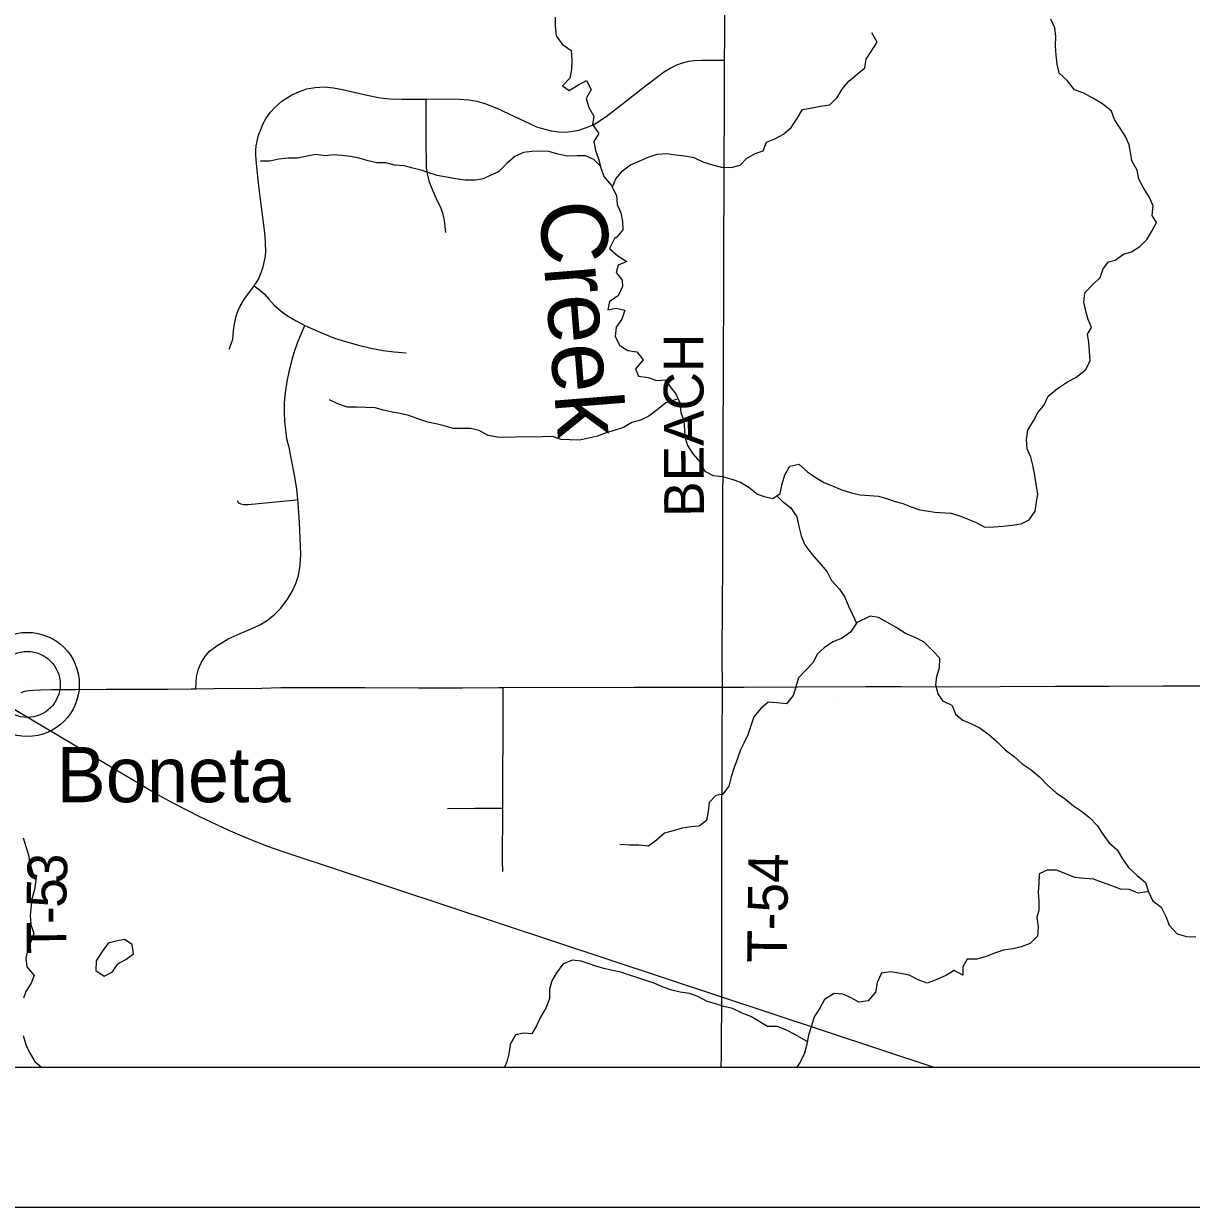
# Model space of a CAD drawing. Extents: x 0 to 34, y 0 to 22.
# Drawn here: x 6.998 to 7.832, y 14 to 14.845 of the extents above; entities that cross this region are included whole.
import ezdxf

# ---------------------------------------------------------------- set-up
doc = ezdxf.new("R2010")
doc.units = 0
for name, color, linetype in [('GM_X_Minor_Lake', 7, 'Continuous'), ('GM_X_Minor_River', 7, 'Continuous'), ('GM_X_Minor_River_Text', 7, 'Continuous'), ('GM_X_Rail_Line', 7, 'Continuous'), ('GM_X_Rail_Line_Text', 7, 'Continuous'), ('GM_X_State_Location', 7, 'Continuous'), ('GM_X_State_Route', 7, 'Continuous'), ('GM_X_Township_Road', 7, 'Continuous'), ('GM_X_Township_Road_Text', 7, 'Continuous'), ('GM_X_Unincorporated', 7, 'Continuous'), ('GM_X_Unincorporated_Location', 7, 'Continuous'), ('GM_X_Unincorporated_Text', 7, 'Continuous'), ('SH_Cut_Line', 7, 'Continuous'), ('SH_Data', 7, 'Continuous')]:
    doc.layers.add(name, color=color, linetype=linetype)

msp = doc.modelspace()

# ---------------------------------------------------------------- linework, layer by layer
at = {"layer": 'GM_X_Minor_Lake'}
for points in [[(7.05816, 14.18868), (7.05377, 14.18268), (7.04953, 14.17596), (7.04928, 14.16913), (7.05523, 14.16507), (7.06125, 14.16821), (7.06493, 14.17397), (7.06498, 14.174)], [(7.05812, 14.18863), (7.05377, 14.18268), (7.04953, 14.17596), (7.04928, 14.16913), (7.05523, 14.16507), (7.06125, 14.16821), (7.06493, 14.17397), (7.06706, 14.17503)], [(7.06699, 14.17502), (7.07076, 14.17693), (7.07618, 14.18101), (7.07529, 14.18783), (7.06973, 14.19133), (7.06349, 14.19007), (7.05798, 14.18863)], [(7.06498, 14.174), (7.07076, 14.17693), (7.07618, 14.18101), (7.07529, 14.18783), (7.06973, 14.19133), (7.06349, 14.19007), (7.05816, 14.18868)]]:
    msp.add_lwpolyline(points, dxfattribs=at)
at = {"layer": 'GM_X_Minor_River'}
for points in [[(7.37743, 14.85002), (7.37727, 14.84357), (7.37806, 14.83675), (7.38243, 14.8307), (7.38889, 14.82618), (7.3893, 14.81973), (7.38914, 14.81272), (7.38783, 14.80645), (7.38256, 14.80112), (7.38749, 14.79773), (7.39353, 14.80155), (7.39977, 14.8048), (7.4032, 14.79837), (7.39963, 14.79191), (7.40155, 14.78547), (7.40498, 14.77942), (7.40406, 14.77335), (7.40863, 14.76711), (7.40506, 14.76122), (7.40622, 14.75496), (7.40833, 14.74891), (7.41006, 14.74247), (7.41216, 14.73622), (7.4173, 14.72999), (7.42112, 14.7228), (7.42171, 14.71617), (7.4242, 14.7103), (7.42555, 14.70424), (7.42576, 14.69817), (7.42105, 14.69246), (7.4201, 14.69246), (7.41616, 14.68486), (7.42205, 14.67958), (7.4285, 14.67562), (7.42227, 14.67294), (7.42096, 14.66763), (7.42515, 14.66234), (7.42555, 14.6576), (7.42236, 14.65095), (7.41631, 14.64694), (7.41501, 14.64106), (7.42088, 14.64222), (7.42713, 14.64092), (7.42507, 14.63447), (7.42093, 14.62857), (7.4202, 14.62212), (7.42364, 14.61569), (7.42933, 14.61193), (7.43577, 14.611), (7.44015, 14.60534), (7.43487, 14.59887), (7.43698, 14.59357), (7.4438, 14.59265), (7.44986, 14.59059), (7.45649, 14.591), (7.45954, 14.58608), (7.46353, 14.58117), (7.4664, 14.57473), (7.46718, 14.56772), (7.46929, 14.56167), (7.46989, 14.55503), (7.46991, 14.55029), (7.47201, 14.54405), (7.47564, 14.53818), (7.48096, 14.53214), (7.4842, 14.5259), (7.49028, 14.5227), (7.4969, 14.52197), (7.50354, 14.5201), (7.5098, 14.51785), (7.51606, 14.51409), (7.52195, 14.50937), (7.52669, 14.50769), (7.53294, 14.5062), (7.53823, 14.50982), (7.53952, 14.51666), (7.54139, 14.52311), (7.54496, 14.52938), (7.55139, 14.53074), (7.55766, 14.52527), (7.56374, 14.52112), (7.56962, 14.51773), (7.58214, 14.51248), (7.58896, 14.51023), (7.59521, 14.50893), (7.60203, 14.50839), (7.60847, 14.50785), (7.61473, 14.50598), (7.61946, 14.50449), (7.62572, 14.50281), (7.6316, 14.50037), (7.63785, 14.49831), (7.64259, 14.49738), (7.64865, 14.49646), (7.6598, 14.49574)], [(7.6598, 14.49574), (7.66018, 14.49571), (7.66683, 14.49372), (7.67294, 14.49131), (7.67771, 14.48946), (7.68421, 14.48592), (7.69068, 14.486), (7.69732, 14.48645), (7.70359, 14.48728), (7.71023, 14.48831), (7.71609, 14.49104), (7.72039, 14.49718), (7.72127, 14.50366), (7.72216, 14.50956), (7.72094, 14.51621), (7.72011, 14.52267), (7.7189, 14.52912), (7.71711, 14.53576), (7.71457, 14.54182), (7.71412, 14.54829), (7.71499, 14.55515), (7.7191, 14.56166), (7.72208, 14.56778), (7.72658, 14.57278), (7.72955, 14.57928), (7.73633, 14.58488), (7.74331, 14.58953), (7.74936, 14.59264), (7.75614, 14.59823), (7.75968, 14.60474), (7.75903, 14.61158), (7.75858, 14.61767), (7.75776, 14.62356), (7.76056, 14.62834), (7.75821, 14.63403), (7.75643, 14.64009), (7.75503, 14.64655), (7.75572, 14.65321), (7.76117, 14.65879), (7.76662, 14.66418), (7.76883, 14.6703), (7.77258, 14.67528), (7.77732, 14.67648), (7.78335, 14.68073), (7.78922, 14.68251), (7.79507, 14.68619), (7.80034, 14.69158), (7.80369, 14.69733), (7.80705, 14.70345), (7.80376, 14.70855), (7.80463, 14.71541), (7.80171, 14.72166), (7.79765, 14.72827), (7.79435, 14.73432), (7.79314, 14.74078), (7.78945, 14.74759), (7.78864, 14.75233), (7.78742, 14.75898), (7.78488, 14.76485), (7.78101, 14.77089), (7.77696, 14.77694), (7.7748, 14.783), (7.76828, 14.78825), (7.76158, 14.79217), (7.75508, 14.79591), (7.7484, 14.79811), (7.74339, 14.80452), (7.73743, 14.80998), (7.73603, 14.81643), (7.73539, 14.82289), (7.73474, 14.82973), (7.73505, 14.83639), (7.73422, 14.84247), (7.73149, 14.84872)], [(7.41801, 14.72861), (7.41844, 14.72901), (7.42069, 14.73455), (7.4254, 14.74045), (7.43125, 14.74464), (7.43749, 14.74714), (7.44391, 14.7502), (7.45034, 14.75231), (7.45715, 14.75272), (7.4636, 14.7518), (7.47004, 14.75107), (7.47648, 14.74977), (7.48293, 14.74676), (7.48975, 14.74452), (7.49619, 14.74284), (7.5032, 14.74268), (7.50944, 14.74441), (7.51415, 14.74917), (7.5202, 14.75261), (7.52606, 14.75472), (7.52831, 14.7608), (7.53435, 14.76329), (7.5404, 14.76654), (7.54587, 14.7713), (7.5502, 14.77777), (7.55415, 14.78404), (7.56096, 14.78539), (7.56701, 14.78656), (7.57363, 14.78753), (7.57872, 14.79268), (7.5823, 14.79876), (7.5872, 14.80428), (7.59323, 14.80942), (7.59871, 14.81399), (7.59944, 14.82006), (7.6032, 14.82558), (7.60753, 14.83223), (7.60371, 14.83885)], [(7.4097, 14.74378), (7.40511, 14.74851), (7.39904, 14.75114), (7.39298, 14.75112), (7.38617, 14.7509), (7.37935, 14.7522), (7.3729, 14.75406), (7.3676, 14.75442), (7.36079, 14.7542), (7.35473, 14.75342), (7.34868, 14.75055), (7.34284, 14.74559), (7.33699, 14.73969), (7.33094, 14.73701), (7.32603, 14.73471), (7.32035, 14.73374), (7.31316, 14.73371), (7.30634, 14.73463), (7.29971, 14.73574), (7.29308, 14.73704), (7.28645, 14.73909), (7.28171, 14.74078), (7.27564, 14.74227), (7.26939, 14.74395), (7.26257, 14.74449), (7.25651, 14.74598), (7.25007, 14.74614), (7.24381, 14.74744), (7.23737, 14.74931), (7.23112, 14.75061), (7.22506, 14.75134), (7.21919, 14.7517), (7.21313, 14.7511), (7.20631, 14.75202), (7.20026, 14.75086), (7.19326, 14.7495), (7.18644, 14.74947), (7.18001, 14.74869), (7.17358, 14.74733), (7.16676, 14.7473)], [(7.4653, 14.57721), (7.46317, 14.57681), (7.45637, 14.57469), (7.45033, 14.56974), (7.44429, 14.56516), (7.43824, 14.56229), (7.43219, 14.56056), (7.42615, 14.55712), (7.42029, 14.55501), (7.41386, 14.55328), (7.40762, 14.55078), (7.40119, 14.54943), (7.39476, 14.54788), (7.38794, 14.54823), (7.38169, 14.5484), (7.37544, 14.55046), (7.36843, 14.55024), (7.34912, 14.55015), (7.34269, 14.54975), (7.33625, 14.5501), (7.32962, 14.5514), (7.32317, 14.55497), (7.31691, 14.55627), (7.31067, 14.55625), (7.30442, 14.55641), (7.29816, 14.55809), (7.29324, 14.55939), (7.28641, 14.56088), (7.27921, 14.56312), (7.27276, 14.56556), (7.2667, 14.56705), (7.26102, 14.56798), (7.25476, 14.56947), (7.2487, 14.57096), (7.24207, 14.57131), (7.23601, 14.57147), (7.22901, 14.57163), (7.22218, 14.57388), (7.21611, 14.57688)], [(7.53574, 14.50812), (7.53938, 14.50452), (7.54565, 14.49962), (7.55003, 14.49319), (7.55157, 14.48618), (7.55312, 14.47974), (7.55579, 14.47331), (7.56074, 14.46651), (7.56607, 14.46065), (7.57158, 14.45385), (7.57483, 14.44761), (7.58053, 14.44156), (7.58434, 14.4357), (7.58702, 14.42946), (7.58969, 14.4234), (7.59275, 14.41735), (7.58842, 14.41088), (7.582, 14.40631), (7.57576, 14.40382), (7.56953, 14.39962), (7.56444, 14.39505), (7.56162, 14.38916), (7.55654, 14.38364), (7.55126, 14.37812), (7.5492, 14.37185), (7.54733, 14.36559), (7.54262, 14.35969), (7.53581, 14.36042), (7.52956, 14.36077), (7.52427, 14.35639), (7.51938, 14.3503), (7.51713, 14.34384), (7.51507, 14.33739), (7.51226, 14.3315), (7.50982, 14.32675), (7.50757, 14.32048), (7.50514, 14.31422), (7.50308, 14.30757), (7.5014, 14.30093), (7.49707, 14.29522), (7.49215, 14.29426), (7.48744, 14.28912), (7.48671, 14.28267), (7.4856, 14.27641), (7.48032, 14.27221), (7.47426, 14.27181), (7.46802, 14.27083), (7.46159, 14.26891), (7.45554, 14.26737), (7.44988, 14.26222), (7.44403, 14.25803), (7.43721, 14.25857), (7.43058, 14.25873), (7.42357, 14.25927)], [(7.66092, 14.35836), (7.6565, 14.36054), (7.65467, 14.36146), (7.65107, 14.36679), (7.64934, 14.37285), (7.65007, 14.37949), (7.65194, 14.38537), (7.65229, 14.3922), (7.64697, 14.39768), (7.64089, 14.40372), (7.63463, 14.4071), (7.62761, 14.40992), (7.62097, 14.41425), (7.61489, 14.41782), (7.60844, 14.42121), (7.60238, 14.42213), (7.59272, 14.41739)], [(7.66092, 14.35836), (7.66329, 14.35215), (7.66865, 14.348), (7.67476, 14.3454), (7.68088, 14.34223), (7.6872, 14.33774), (7.69315, 14.33248), (7.69891, 14.32684), (7.70524, 14.32196), (7.711, 14.31689), (7.71751, 14.31259), (7.72346, 14.30752), (7.72904, 14.30149), (7.73537, 14.29605), (7.74189, 14.29156), (7.74764, 14.28686), (7.75339, 14.28293), (7.75914, 14.27843), (7.76452, 14.27279), (7.76858, 14.26655), (7.77283, 14.26051), (7.77878, 14.25525), (7.78265, 14.24902), (7.7869, 14.24279), (7.79305, 14.23696), (7.799, 14.23208), (7.80117, 14.22526), (7.80408, 14.2192), (7.81022, 14.21451), (7.81353, 14.2077), (7.81607, 14.20145), (7.82184, 14.19524), (7.82832, 14.19341), (7.83517, 14.19311)], [(6.9974, 14.26388), (6.99913, 14.25782), (7.00124, 14.25177), (7.00221, 14.2457), (7.00394, 14.23964), (7.00643, 14.23321), (7.00532, 14.22695), (7.00345, 14.22011), (7.00291, 14.21329), (7.00236, 14.20855), (7.00277, 14.2021), (7.00488, 14.19566), (7.00319, 14.19092), (7.00076, 14.18446), (6.99927, 14.17801), (7.00005, 14.17176), (7.00519, 14.16552), (7.00294, 14.16001), (6.99918, 14.15412), (6.99749, 14.14937)], [(7.80104, 14.22564), (7.8004, 14.22544), (7.79395, 14.22441), (7.78765, 14.22701), (7.78119, 14.22731), (7.77508, 14.22953), (7.7684, 14.23211), (7.76191, 14.23432), (7.75544, 14.23482), (7.74859, 14.2355), (7.7421, 14.23809), (7.73561, 14.24088), (7.72877, 14.2408), (7.72309, 14.23826), (7.72279, 14.23122), (7.72248, 14.22512), (7.72293, 14.21847), (7.72281, 14.212), (7.72154, 14.20723), (7.72237, 14.20039), (7.72207, 14.19373), (7.71662, 14.18834), (7.71018, 14.18617), (7.70449, 14.18459), (7.69766, 14.18375), (7.69198, 14.18178), (7.68536, 14.17904), (7.67854, 14.17725), (7.67169, 14.17717), (7.66871, 14.17181), (7.66859, 14.16572), (7.66247, 14.16915)], [(7.55742, 14.11833), (7.55534, 14.11973), (7.54908, 14.12311), (7.54263, 14.1265), (7.53618, 14.12912), (7.52917, 14.1291), (7.5231, 14.13267), (7.51722, 14.13625), (7.51096, 14.13869), (7.50413, 14.14207), (7.49788, 14.14337), (7.492, 14.14524), (7.48594, 14.14711), (7.4793, 14.15068), (7.47323, 14.15274), (7.4666, 14.15366), (7.46073, 14.15515), (7.4539, 14.15759), (7.44802, 14.16003), (7.44139, 14.16227), (7.4357, 14.16415), (7.42906, 14.16639), (7.42432, 14.16808), (7.41959, 14.16901), (7.41315, 14.17031), (7.40708, 14.17199), (7.40101, 14.17423), (7.39589, 14.17592), (7.38964, 14.17665), (7.38284, 14.17378), (7.37832, 14.1675), (7.37494, 14.1618), (7.37326, 14.15573), (7.37329, 14.14909), (7.37085, 14.14263), (7.3669, 14.13579), (7.36409, 14.12952), (7.36071, 14.12382), (7.35483, 14.12437), (7.34916, 14.1232), (7.34521, 14.11636), (7.34429, 14.10972), (7.3428, 14.10384), (7.34119, 14.1)], [(7.66243, 14.16911), (7.65644, 14.16547), (7.64963, 14.1626), (7.64321, 14.16011), (7.63676, 14.16254), (7.63031, 14.16593), (7.62406, 14.16704), (7.61724, 14.16815), (7.61062, 14.16736), (7.60742, 14.16052), (7.60613, 14.15369), (7.60104, 14.14741), (7.59442, 14.14644), (7.58873, 14.14964), (7.58285, 14.15227), (7.5766, 14.15281), (7.5698, 14.14842), (7.56642, 14.14215), (7.56247, 14.13606), (7.56041, 14.12961), (7.55836, 14.12296), (7.55706, 14.11651), (7.55557, 14.11006), (7.55256, 14.10417), (7.54994, 14.1)], [(6.99741, 14.12283), (6.99933, 14.11639), (7.00182, 14.11053), (7.00563, 14.1041), (7.01037, 14.1)]]:
    msp.add_lwpolyline(points, dxfattribs=at)
at = {"layer": 'GM_X_Rail_Line'}
msp.add_lwpolyline([(6.98377, 14.36021), (7.05376, 14.31836), (7.09383, 14.29471), (7.1037, 14.28919), (7.12323, 14.2791), (7.14348, 14.26967), (7.15519, 14.26466), (7.17118, 14.25825), (7.1842, 14.25368), (7.64795, 14.1)], dxfattribs=at)
at = {"layer": 'GM_X_Rail_Line_Text'}
msp.add_lwpolyline([(6.7466, 14.1), (8.9, 14.1), (8.9, 15.65232), (8.85084, 15.65219), (8.81714, 15.6521), (8.55432, 15.65138), (8.38107, 15.65063), (8.0395, 15.64944), (7.56787, 15.64626), (7.49589, 15.64556), (7.47838, 15.64609), (7.17478, 15.64453), (6.99923, 15.64397), (6.98283, 15.64326), (6.74001, 15.64147), (6.73918, 15.60382), (6.74001, 15.34907), (6.73934, 15.12764), (6.74144, 15.02092), (6.74201, 15.01654), (6.74627, 14.37116), (6.74627, 14.36613)], close=True, dxfattribs=at)
at = {"layer": 'GM_X_State_Route'}
for points in [[(6.99585, 14.36772), (6.99778, 14.36839), (6.99958, 14.36887), (7.00168, 14.36923), (7.00457, 14.36948), (7.01005, 14.3697), (7.01752, 14.36983), (7.03477, 14.36996), (7.05656, 14.36999), (7.0807, 14.37009), (7.10056, 14.37018), (7.11737, 14.37037), (7.12057, 14.37041), (7.13378, 14.3706), (7.16784, 14.37093), (7.18147, 14.37118), (7.24135, 14.37139), (7.27972, 14.37113), (7.31099, 14.37104), (7.33692, 14.37124), (7.34024, 14.37129), (7.43379, 14.3715), (7.48369, 14.37164), (7.49701, 14.37158), (7.51232, 14.37153), (7.5507, 14.37167), (7.59943, 14.37202), (7.62426, 14.37191), (7.65736, 14.37184), (7.6954, 14.37198), (7.7349, 14.37218)], [(7.7349, 14.37218), (7.7364, 14.37219), (7.77347, 14.37222), (7.81137, 14.37239), (7.84982, 14.37253), (7.89319, 14.3724)]]:
    msp.add_lwpolyline(points, dxfattribs=at)
at = {"layer": 'GM_X_Township_Road'}
for points in [[(7.49701, 14.37158), (7.49677, 14.39361), (7.49686, 14.43165), (7.49709, 14.45727), (7.49722, 14.49594), (7.49745, 14.5382), (7.49763, 14.60644), (7.4978, 14.65269), (7.49794, 14.69899), (7.49802, 14.71823), (7.49818, 14.75485), (7.49826, 14.7752), (7.49844, 14.81934), (7.49849, 14.83606), (7.49856, 14.85497)], [(7.14452, 14.61293), (7.14599, 14.61665), (7.14714, 14.62018), (7.14762, 14.62636), (7.14831, 14.63096), (7.14959, 14.63653), (7.1508, 14.64016), (7.15235, 14.64376), (7.15536, 14.64895), (7.15917, 14.654), (7.16247, 14.65819), (7.16509, 14.66251), (7.1672, 14.66708), (7.16886, 14.67182), (7.17034, 14.67929), (7.17076, 14.68306), (7.17017, 14.69413), (7.16903, 14.70347), (7.16671, 14.7217), (7.16529, 14.73385), (7.16377, 14.74793), (7.16346, 14.75194), (7.16356, 14.75509), (7.16387, 14.7582), (7.16439, 14.76162), (7.16554, 14.76591), (7.16706, 14.76979), (7.16889, 14.77408), (7.171, 14.77788), (7.17394, 14.78228), (7.17744, 14.78591), (7.18221, 14.79009), (7.18927, 14.79456), (7.19473, 14.79705), (7.20006, 14.79892), (7.20591, 14.79989), (7.21265, 14.80027), (7.21909, 14.79971), (7.22545, 14.79843), (7.2431, 14.79445), (7.2523, 14.79255), (7.25956, 14.79172), (7.2679, 14.79162), (7.28517, 14.79145), (7.30128, 14.79186), (7.30907, 14.79162), (7.31582, 14.79103), (7.32142, 14.79006), (7.32716, 14.78833), (7.33577, 14.78515), (7.34795, 14.77944), (7.35916, 14.77411), (7.36414, 14.77186), (7.36913, 14.77024), (7.37442, 14.76899), (7.37999, 14.76823), (7.38421, 14.76799), (7.38853, 14.76837), (7.39417, 14.76948), (7.39977, 14.77128), (7.40441, 14.77318), (7.40811, 14.77532), (7.41465, 14.77985), (7.42766, 14.78996), (7.44067, 14.80013), (7.45471, 14.81078), (7.45952, 14.81355), (7.4644, 14.81594), (7.46845, 14.81739), (7.47284, 14.8186), (7.47682, 14.81919), (7.48194, 14.81936), (7.49166, 14.81947), (7.49844, 14.81934)], [(7.29937, 14.69626), (7.29825, 14.70481), (7.29739, 14.70908), (7.29588, 14.71332), (7.29258, 14.72043), (7.29003, 14.72629), (7.28762, 14.73235), (7.2864, 14.73728), (7.28554, 14.7423), (7.28543, 14.74708), (7.28525, 14.75929), (7.28529, 14.77699), (7.28525, 14.78658), (7.28517, 14.79145)], [(7.16247, 14.65819), (7.16626, 14.65538), (7.16981, 14.65226), (7.17283, 14.64866), (7.17653, 14.64448), (7.18177, 14.63993), (7.18664, 14.63654), (7.19246, 14.63331), (7.19862, 14.62987), (7.20829, 14.62548), (7.21977, 14.62093), (7.22766, 14.61834), (7.23686, 14.61574), (7.24576, 14.61363), (7.25454, 14.61209), (7.26243, 14.61108), (7.27105, 14.61029)], [(7.12057, 14.37041), (7.12122, 14.37896), (7.1226, 14.38457), (7.12445, 14.38901), (7.12715, 14.39324), (7.13049, 14.39732), (7.13562, 14.40113), (7.14366, 14.40595), (7.1524, 14.40976), (7.16018, 14.41315), (7.16695, 14.41632), (7.17187, 14.41934), (7.17695, 14.42352), (7.18129, 14.42802), (7.18611, 14.43431), (7.18939, 14.43987), (7.19204, 14.44554), (7.19394, 14.4512), (7.19511, 14.45877), (7.19569, 14.4666), (7.19479, 14.48925), (7.19373, 14.50328), (7.19351, 14.50557), (7.19283, 14.51291), (7.19146, 14.52183), (7.18929, 14.53275), (7.18749, 14.54186), (7.18579, 14.54884), (7.18495, 14.5553), (7.18421, 14.56096), (7.18399, 14.56827), (7.1841, 14.57478), (7.18468, 14.58171), (7.18585, 14.58991), (7.18743, 14.59685), (7.1895, 14.60558), (7.19108, 14.61119), (7.19341, 14.61749), (7.19622, 14.62447), (7.19862, 14.62987)], [(7.15011, 14.50489), (7.15123, 14.50328), (7.15271, 14.50259), (7.15499, 14.50206), (7.15816, 14.5019), (7.19019, 14.50513), (7.19351, 14.50557)], [(7.34001, 14.23979), (7.33986, 14.24716), (7.33981, 14.2597), (7.34006, 14.27156), (7.33995, 14.28521), (7.33999, 14.30085), (7.3401, 14.31346), (7.34024, 14.33223), (7.34019, 14.35638), (7.34012, 14.3611), (7.34024, 14.37129)], [(7.49599, 14.1), (7.4961, 14.10868), (7.49616, 14.11776), (7.49635, 14.14547), (7.49638, 14.15012), (7.49642, 14.18504), (7.49646, 14.22573), (7.49637, 14.27221), (7.49659, 14.31582), (7.49668, 14.33208), (7.49701, 14.37158)], [(7.30041, 14.28498), (7.31993, 14.28509), (7.33995, 14.28521)]]:
    msp.add_lwpolyline(points, dxfattribs=at)
at = {"layer": 'GM_X_Unincorporated'}
for radius in [0.0372, 0.02358]:
    msp.add_circle((7.00024, 14.37349), radius, dxfattribs=at)
at = {"layer": 'GM_X_Unincorporated_Location'}
msp.add_line((7.00024, 14.37349), (7.00024, 14.37349), dxfattribs=at)
at = {"layer": 'SH_Cut_Line'}
msp.add_lwpolyline([(2.1, 14.1), (8.9, 14.1), (8.9, 20.52117), (8.88492, 20.52095), (8.78844, 20.51908), (8.45204, 20.51253), (8.41696, 20.51215), (8.39386, 20.51177), (8.38319, 20.51123), (8.37874, 20.51114), (8.37504, 20.51102), (8.18847, 20.50622), (7.95771, 20.5026), (7.74412, 20.50184), (7.55552, 20.49834), (7.41076, 20.49536), (7.12851, 20.48984), (7.05001, 20.48828), (6.99108, 20.48711)], dxfattribs=at)
at = {"layer": 'SH_Data'}
for p, q in [((2.1, 14.1), (8.9, 14.1)), ((2, 14), (9, 14))]:
    msp.add_line(p, q, dxfattribs=at)

# ---------------------------------------------------------------- texts
at = {"layer": 'GM_X_Minor_River_Text'}
msp.add_text('Creek', height=0.047374, rotation=274.59176, dxfattribs=at).set_placement((7.36581, 14.71737))
at = {"layer": 'GM_X_State_Location'}
for s, p in [('s', (7.57621, 14.36058)), ('r', (7.5762, 14.36058))]:
    msp.add_text(s, height=0.0000947, dxfattribs=at).set_placement(p)
msp.add_text('162', height=0.0000947, rotation=0.00001, dxfattribs=at).set_placement((7.54278, 14.35369))
at = {"layer": 'GM_X_Township_Road_Text'}
for s, height, rotation, p in [('BEACH', 0.028409, 90.20382, (7.48369, 14.49321)), ('3', 0.02841, 87.68359, (7.02839, 14.23115)), ('T-54', 0.028409, 89.29173, (7.54292, 14.1746)), ('5', 0.02841, 89.15173, (7.02813, 14.21384)), ('-', 0.02841, 90.07807, (7.02815, 14.20229)), ('T', 0.02841, 90.50571, (7.02834, 14.1811))]:
    msp.add_text(s, height=height, rotation=rotation, dxfattribs=at).set_placement(p)
at = {"layer": 'GM_X_Unincorporated_Text'}
msp.add_text('Boneta', height=0.039489, rotation=0.00001, dxfattribs=at).set_placement((7.02111, 14.28936))

doc.saveas('drawing.dxf')
